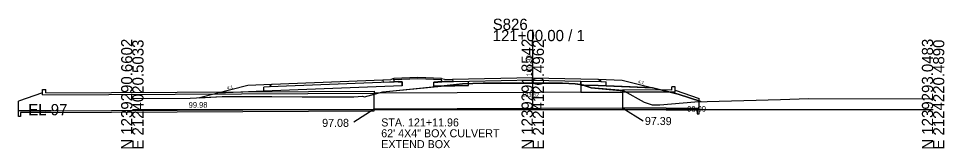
# Model space of a CAD drawing. Extents: x 2119282 to 2119710, y 1215030 to 1220057.
# Drawn here: x 2119379.2 to 2119610.4, y 1219530.1 to 1219562.5 of the extents above; entities that cross this region are included whole.
import ezdxf

# ---------------------------------------------------------------- set-up
doc = ezdxf.new("R2010")
doc.units = 0
for name, color, linetype in [('TS_CURB_GUTTER', 7, 'Continuous'), ('X_DRAINAGE_PIPES', 7, 'Continuous'), ('XS_CELL', 7, 'Continuous'), ('XS_M_SHAPES_EARTHWORK', 7, 'Continuous'), ('XS_P_CONCRETE', 7, 'Continuous'), ('XS_P_DRAINAGE', 7, 'Continuous'), ('XS_P_FINISHED_GRADE', 7, 'Continuous'), ('XS_P_FINISHED_GRADE_ELEV_TX', 7, 'Continuous'), ('XS_P_SUBGRADE_GRANULAR', 7, 'Continuous'), ('XS_P_SUBGRADE_LEVELING', 7, 'Continuous'), ('XS_P_SUBGRADE_PAVEMENT', 7, 'Continuous'), ('XS_P_TX_DCH', 7, 'Continuous'), ('XS_P_TX_FS_BS', 7, 'Continuous'), ('XS_X_GROUND', 7, 'Continuous'), ('XS_X_GROUND_TX', 7, 'Continuous')]:
    doc.layers.add(name, color=color, linetype=linetype)

msp = doc.modelspace()

# ---------------------------------------------------------------- linework, layer by layer
at = {"layer": 'TS_CURB_GUTTER'}
for points in [[(2119470.19, 1219547.17), (2119470.21, 1219546.67), (2119472.96, 1219546.78), (2119472.94, 1219547.59), (2119472.94, 1219547.6), (2119472.93, 1219547.6), (2119472.93, 1219547.61), (2119472.92, 1219547.6), (2119472.24, 1219547.35), (2119472.21, 1219547.33), (2119472.2, 1219547.3), (2119472.19, 1219547.27), (2119472.19, 1219547.25), (2119470.19, 1219547.17)], [(2119487.6, 1219547.33), (2119487.61, 1219546.83), (2119484.86, 1219546.78), (2119484.84, 1219547.59), (2119484.84, 1219547.6), (2119484.84, 1219547.6), (2119484.84, 1219547.61), (2119484.85, 1219547.61), (2119485.54, 1219547.39), (2119485.57, 1219547.38), (2119485.6, 1219547.35), (2119485.6, 1219547.31), (2119485.6, 1219547.29), (2119487.6, 1219547.33)]]:
    msp.add_lwpolyline(points, dxfattribs=at)
at = {"layer": 'X_DRAINAGE_PIPES'}
for p, q in [((2119530.1, 1219544.19), (2119468, 1219543.88)), ((2119468, 1219539.88), (2119468, 1219543.88)), ((2119530.1, 1219540.19), (2119530.1, 1219544.19)), ((2119468, 1219539.88), (2119462.91, 1219536.69)), ((2119530.1, 1219540.19), (2119468, 1219539.88)), ((2119530.1, 1219540.19), (2119535.2, 1219537))]:
    msp.add_line(p, q, dxfattribs=at)
at = {"layer": 'XS_CELL'}
for p, q in [((2119507.6, 1219539.8), (2119507.6, 1219559.69)), ((2119407.6, 1219539.8), (2119507.6, 1219539.8)), ((2119507.6, 1219539.8), (2119607.6, 1219539.8))]:
    msp.add_line(p, q, dxfattribs=at)
at = {"layer": 'XS_M_SHAPES_EARTHWORK'}
for p, q in [((2119474.96, 1219545.77), (2119442.54, 1219544.48)), ((2119470.2, 1219544.28), (2119484.7, 1219545.69)), ((2119478.89, 1219547.5), (2119472.95, 1219547.26)), ((2119472.95, 1219547.26), (2119472.96, 1219546.78)), ((2119472.96, 1219546.78), (2119473.96, 1219546.82)), ((2119473.96, 1219546.82), (2119474.01, 1219546.74)), ((2119474.01, 1219546.74), (2119474.96, 1219546.77)), ((2119474.96, 1219546.77), (2119474.96, 1219545.77)), ((2119484.85, 1219547.26), (2119478.89, 1219547.5)), ((2119482.86, 1219546.65), (2119483.87, 1219546.67)), ((2119482.86, 1219545.65), (2119482.86, 1219546.65)), ((2119484.7, 1219545.69), (2119482.86, 1219545.65)), ((2119483.87, 1219546.67), (2119483.92, 1219546.76)), ((2119483.92, 1219546.76), (2119484.86, 1219546.78)), ((2119490.03, 1219546.21), (2119484.7, 1219545.69)), ((2119484.7, 1219545.69), (2119491.55, 1219545.83)), ((2119484.86, 1219546.78), (2119484.85, 1219547.26)), ((2119491.55, 1219546.27), (2119490.03, 1219546.21)), ((2119491.55, 1219545.83), (2119491.55, 1219546.27)), ((2119519.97, 1219546.03), (2119519.6, 1219546.08)), ((2119519.6, 1219546.08), (2119519.6, 1219545.91)), ((2119519.6, 1219545.91), (2119520.37, 1219545.89)), ((2119520.37, 1219545.89), (2119519.6, 1219545.91)), ((2119519.6, 1219545.91), (2119519.6, 1219544.14)), ((2119520.37, 1219545.89), (2119519.97, 1219546.03)), ((2119522.22, 1219545.26), (2119520.37, 1219545.89)), ((2119523.95, 1219545.82), (2119520.37, 1219545.89)), ((2119520.37, 1219545.89), (2119522.22, 1219545.26)), ((2119525.95, 1219545.74), (2119523.95, 1219545.82)), ((2119531.95, 1219545.5), (2119525.95, 1219545.74)), ((2119428.93, 1219543.93), (2119424.34, 1219542.78)), ((2119440.47, 1219544.39), (2119428.93, 1219543.93)), ((2119442.54, 1219544.48), (2119440.47, 1219544.39)), ((2119465.59, 1219543.01), (2119468, 1219543.68)), ((2119468, 1219543.88), (2119468.77, 1219543.89)), ((2119468, 1219543.68), (2119468, 1219543.88)), ((2119468.77, 1219543.89), (2119470.2, 1219544.28)), ((2119519.6, 1219544.14), (2119530.1, 1219544.19)), ((2119530.12, 1219544.55), (2119522.22, 1219545.26)), ((2119530.1, 1219544.19), (2119530.12, 1219544.19)), ((2119530.1, 1219544.19), (2119530.12, 1219544.19)), ((2119530.12, 1219544.19), (2119530.12, 1219544.55)), ((2119530.38, 1219544.53), (2119535.4, 1219541.63)), ((2119537.49, 1219545.28), (2119531.95, 1219545.5)), ((2119543.95, 1219543.67), (2119537.49, 1219545.28)), ((2119549.56, 1219541.8), (2119543.95, 1219543.67)), ((2119424.34, 1219542.78), (2119430.05, 1219543.12)), ((2119430.05, 1219543.12), (2119442.44, 1219543.11)), ((2119442.44, 1219543.11), (2119450.04, 1219543)), ((2119450.04, 1219543), (2119462.95, 1219543.03)), ((2119462.95, 1219543.03), (2119465.11, 1219543.14)), ((2119465.11, 1219543.14), (2119465.59, 1219543.01)), ((2119535.4, 1219541.63), (2119537.45, 1219541.04)), ((2119537.45, 1219541.04), (2119539.34, 1219540.97)), ((2119539.34, 1219540.97), (2119548.05, 1219541.75)), ((2119548.05, 1219541.75), (2119549.56, 1219541.8))]:
    msp.add_line(p, q, dxfattribs=at)
msp.add_lwpolyline([(2119522.22, 1219545.26), (2119530.12, 1219544.55), (2119530.38, 1219544.53)], dxfattribs=at)
at = {"layer": 'XS_P_CONCRETE'}
for p, q in [((2119478.89, 1219547.5), (2119472.95, 1219547.26)), ((2119484.85, 1219547.26), (2119478.89, 1219547.5))]:
    msp.add_line(p, q, dxfattribs=at)
at = {"layer": 'XS_P_DRAINAGE'}
for p, q in [((2119385.17, 1219544.01), (2119379.17, 1219541.89)), ((2119385.17, 1219544.84), (2119386, 1219544.85)), ((2119385.17, 1219543.47), (2119385.17, 1219544.84)), ((2119385.17, 1219543.47), (2119468, 1219543.88)), ((2119386, 1219544.01), (2119386, 1219544.85)), ((2119386, 1219544.01), (2119468, 1219544.42)), ((2119468, 1219544.42), (2119468, 1219543.88)), ((2119530.13, 1219544.73), (2119530.12, 1219544.19)), ((2119543.14, 1219544.13), (2119530.12, 1219544.19)), ((2119542.31, 1219544.67), (2119530.13, 1219544.73)), ((2119542.31, 1219544.67), (2119542.31, 1219545.51)), ((2119543.14, 1219545.5), (2119542.31, 1219545.51)), ((2119543.14, 1219544.13), (2119543.14, 1219545.5)), ((2119543.14, 1219544.67), (2119549.14, 1219542.55)), ((2119379.17, 1219539.48), (2119379.17, 1219541.89)), ((2119549.14, 1219540.14), (2119549.14, 1219542.55)), ((2119379.17, 1219539.06), (2119379.17, 1219539.48)), ((2119387.34, 1219539.48), (2119379.17, 1219539.48)), ((2119379.17, 1219538.06), (2119379.17, 1219539.06)), ((2119387.34, 1219539.06), (2119379.67, 1219539.06)), ((2119379.67, 1219539.06), (2119379.67, 1219538.06)), ((2119386, 1219539.47), (2119468, 1219539.88)), ((2119386, 1219539.06), (2119468, 1219539.47)), ((2119468, 1219539.47), (2119468, 1219539.88)), ((2119540.97, 1219540.14), (2119530.1, 1219540.19)), ((2119530.1, 1219539.78), (2119530.1, 1219540.19)), ((2119540.97, 1219539.72), (2119530.1, 1219539.78)), ((2119540.97, 1219540.14), (2119549.14, 1219540.14)), ((2119540.97, 1219539.72), (2119548.64, 1219539.72)), ((2119548.64, 1219539.72), (2119548.64, 1219538.72)), ((2119548.64, 1219538.72), (2119549.14, 1219538.72)), ((2119549.14, 1219539.72), (2119549.14, 1219540.14)), ((2119549.14, 1219538.72), (2119549.14, 1219539.72)), ((2119379.67, 1219538.06), (2119379.17, 1219538.06))]:
    msp.add_line(p, q, dxfattribs=at)
at = {"layer": 'XS_P_FINISHED_GRADE'}
for p, q in [((2119436.47, 1219545.82), (2119424.34, 1219542.78)), ((2119442.47, 1219546.06), (2119436.47, 1219545.82)), ((2119470.19, 1219547.17), (2119442.47, 1219546.06)), ((2119478.89, 1219547.83), (2119472.94, 1219547.59)), ((2119484.84, 1219547.59), (2119478.89, 1219547.83)), ((2119507.6, 1219547.73), (2119487.6, 1219547.33)), ((2119507.6, 1219547.73), (2119519.6, 1219547.49)), ((2119519.6, 1219547.49), (2119523.95, 1219547.41)), ((2119523.95, 1219547.41), (2119529.95, 1219547.17)), ((2119525.95, 1219545.74), (2119531.95, 1219545.5)), ((2119529.95, 1219547.17), (2119543.95, 1219543.67)), ((2119543.95, 1219543.67), (2119549.56, 1219541.8))]:
    msp.add_line(p, q, dxfattribs=at)
at = {"layer": 'XS_P_SUBGRADE_GRANULAR'}
for p, q in [((2119474.96, 1219545.77), (2119442.54, 1219544.48)), ((2119474.96, 1219546.77), (2119474.01, 1219546.74)), ((2119474.96, 1219545.77), (2119474.96, 1219546.77)), ((2119483.87, 1219546.67), (2119482.86, 1219546.65)), ((2119482.86, 1219545.65), (2119482.86, 1219546.65)), ((2119491.55, 1219545.83), (2119482.86, 1219545.65)), ((2119491.55, 1219545.83), (2119491.55, 1219546.27)), ((2119519.6, 1219545.91), (2119519.6, 1219546.91)), ((2119519.6, 1219545.91), (2119523.95, 1219545.82)), ((2119523.95, 1219545.82), (2119525.95, 1219545.74)), ((2119524.6, 1219546.81), (2119525.95, 1219546.75)), ((2119525.95, 1219545.74), (2119525.95, 1219546.75)), ((2119525.95, 1219545.74), (2119537.49, 1219545.28)), ((2119440.47, 1219544.39), (2119428.93, 1219543.93)), ((2119441.84, 1219545.45), (2119440.47, 1219545.39)), ((2119440.47, 1219544.39), (2119440.47, 1219545.39)), ((2119442.54, 1219544.48), (2119440.47, 1219544.39))]:
    msp.add_line(p, q, dxfattribs=at)
at = {"layer": 'XS_P_SUBGRADE_LEVELING'}
for p, q in [((2119491.55, 1219546.27), (2119491.55, 1219546.83)), ((2119492.63, 1219546.31), (2119491.55, 1219546.27)), ((2119495.23, 1219546.41), (2119492.63, 1219546.31)), ((2119501.42, 1219546.42), (2119495.23, 1219546.41)), ((2119507.6, 1219546.42), (2119501.42, 1219546.42)), ((2119511.31, 1219546.43), (2119507.6, 1219546.42)), ((2119515.02, 1219546.43), (2119511.31, 1219546.43)), ((2119518.2, 1219546.27), (2119515.02, 1219546.43)), ((2119519.6, 1219546.08), (2119518.2, 1219546.27)), ((2119519.6, 1219546.91), (2119519.6, 1219546.08))]:
    msp.add_line(p, q, dxfattribs=at)
at = {"layer": 'XS_P_SUBGRADE_PAVEMENT'}
for p, q in [((2119474.01, 1219546.74), (2119441.84, 1219545.45)), ((2119441.99, 1219545.7), (2119441.84, 1219545.45)), ((2119442.47, 1219546.06), (2119441.99, 1219545.7)), ((2119473.96, 1219546.82), (2119472.96, 1219546.78)), ((2119473.96, 1219546.82), (2119474.01, 1219546.74)), ((2119507.6, 1219547.15), (2119483.87, 1219546.67)), ((2119483.87, 1219546.67), (2119483.92, 1219546.76)), ((2119484.86, 1219546.78), (2119483.92, 1219546.76)), ((2119507.6, 1219547.15), (2119519.6, 1219546.91)), ((2119519.6, 1219546.91), (2119524.6, 1219546.81)), ((2119523.95, 1219547.41), (2119524.45, 1219547.06)), ((2119524.45, 1219547.06), (2119524.6, 1219546.81))]:
    msp.add_line(p, q, dxfattribs=at)
at = {"layer": 'XS_X_GROUND'}
for p, q in [((2119470.2, 1219544.28), (2119490.03, 1219546.21)), ((2119490.03, 1219546.21), (2119495.23, 1219546.41)), ((2119495.23, 1219546.41), (2119507.6, 1219546.42)), ((2119507.6, 1219546.42), (2119515.02, 1219546.43)), ((2119515.02, 1219546.43), (2119518.2, 1219546.27)), ((2119518.2, 1219546.27), (2119519.97, 1219546.03)), ((2119519.97, 1219546.03), (2119522.22, 1219545.26)), ((2119465.59, 1219543.01), (2119470.2, 1219544.28)), ((2119522.22, 1219545.26), (2119530.38, 1219544.53)), ((2119530.38, 1219544.53), (2119535.4, 1219541.63)), ((2119407.6, 1219542.56), (2119422.08, 1219542.65)), ((2119422.08, 1219542.65), (2119430.05, 1219543.12)), ((2119430.05, 1219543.12), (2119442.44, 1219543.11)), ((2119442.44, 1219543.11), (2119450.04, 1219543)), ((2119450.04, 1219543), (2119462.95, 1219543.03)), ((2119462.95, 1219543.03), (2119465.11, 1219543.14)), ((2119465.11, 1219543.14), (2119465.59, 1219543.01)), ((2119535.4, 1219541.63), (2119537.45, 1219541.04)), ((2119537.45, 1219541.04), (2119539.34, 1219540.97)), ((2119539.34, 1219540.97), (2119548.05, 1219541.75)), ((2119548.05, 1219541.75), (2119569.52, 1219542.36)), ((2119569.52, 1219542.36), (2119576.47, 1219542.62)), ((2119576.47, 1219542.62), (2119607.6, 1219542.48))]:
    msp.add_line(p, q, dxfattribs=at)

# ---------------------------------------------------------------- texts
at = {"layer": 'X_DRAINAGE_PIPES'}
for s, p in [('97.08', (2119455.01, 1219535.5)), ('STA. 121+11.96', (2119469.76, 1219535.61)), ('62\' 4X4" BOX CULVERT', (2119469.76, 1219532.9)), ('EXTEND BOX ', (2119469.76, 1219530.19))]:
    msp.add_text(s, height=2, dxfattribs=at).set_placement(p)
msp.add_text('97.39', height=2, rotation=359.545, dxfattribs=at).set_placement((2119535.6, 1219535.99))
at = {"layer": 'XS_CELL'}
for s, p in [('S826', (2119497.6, 1219559.69)), ('121+00.00 / 1', (2119497.6, 1219556.89)), ('EL 97', (2119381.6, 1219538.4))]:
    msp.add_text(s, height=2.8, dxfattribs=at).set_placement(p)
for s, p in [('N 1239290.6602', (2119407.6, 1219529.8)), ('E 2124020.5033', (2119410.4, 1219529.8)), ('N 1239291.8542', (2119507.6, 1219529.8)), ('N 1239293.0483', (2119607.6, 1219529.8)), ('E 2124220.4890', (2119610.4, 1219529.8)), ('E 2124120.4962', (2119510.4, 1219529.8))]:
    msp.add_text(s, height=2.8, rotation=90, dxfattribs=at).set_placement(p)
at = {"layer": 'XS_P_FINISHED_GRADE_ELEV_TX'}
msp.add_text('104.93', height=1.25, rotation=90, dxfattribs=at).set_placement((2119507.3, 1219548.14))
at = {"layer": 'XS_P_TX_DCH'}
for s, p in [('99.98', (2119421.67, 1219540.28)), ('98.99', (2119546.2, 1219539.29))]:
    msp.add_text(s, height=1.4, dxfattribs=at).set_placement(p)
at = {"layer": 'XS_P_TX_FS_BS'}
for rotation, p in [(14.0362, (2119431.33, 1219544.77)), (345.9638, (2119533.83, 1219546.48))]:
    msp.add_text('4:1', height=0.8, rotation=rotation, dxfattribs=at).set_placement(p)
at = {"layer": 'XS_X_GROUND_TX'}
msp.add_text('103.62', height=1, dxfattribs=at).set_placement((2119504.96, 1219543))

doc.saveas('drawing.dxf')
